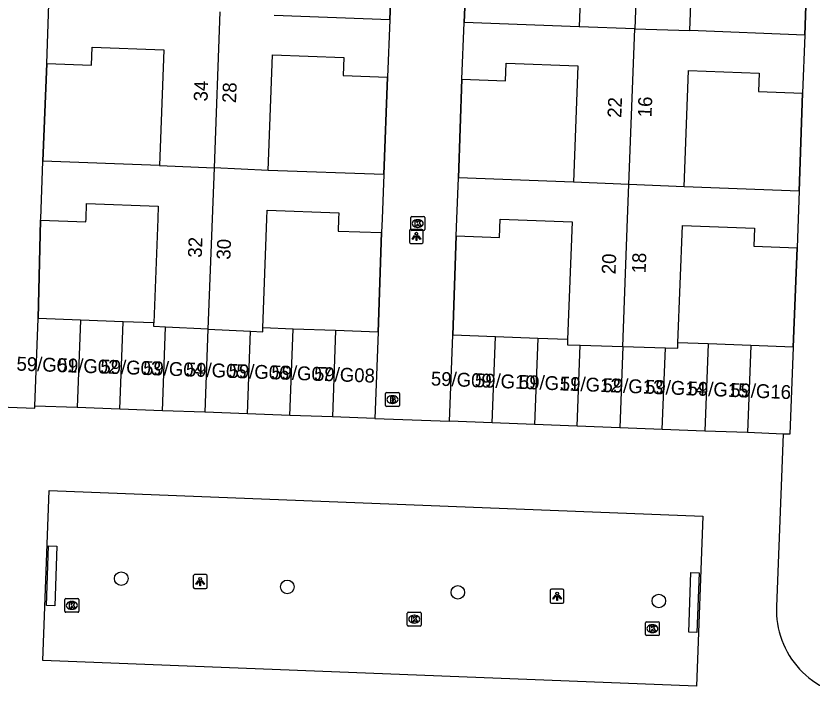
# Model space of a CAD drawing. Extents: x 160787 to 161428, y 386828 to 387483.
# Drawn here: x 161176.3 to 161233.8, y 387215.5 to 387264.6 of the extents above; entities that cross this region are included whole.
import ezdxf

# ---------------------------------------------------------------- set-up
doc = ezdxf.new("R2010")
doc.units = 0
for name, color, linetype in [('IMGEO_Boom', 7, 'Continuous'), ('IMGEO_Brandkraan', 7, 'Continuous'), ('IMGEO_Kolk', 7, 'Continuous'), ('IMGEO_Lichtpunt', 7, 'Continuous'), ('IMGEO_Muur', 7, 'Continuous'), ('IMGEO_Pand', 7, 'Continuous'), ('IMGEO_Pand_nummerreeks', 7, 'Continuous'), ('IMGEO_Parkeervlak_open', 7, 'Continuous'), ('IMGEO_Rijbaan_lokaal_open', 7, 'Continuous'), ('IMGEO_Voetpad_open', 7, 'Continuous')]:
    doc.layers.add(name, color=color, linetype=linetype)

msp = doc.modelspace()

# ---------------------------------------------------------------- linework, layer by layer
at = {"layer": 'IMGEO_Boom'}
for centre in [(161183.943, 387224.022), (161195.925, 387223.425), (161208.239, 387223.031), (161222.747, 387222.414)]:
    msp.add_circle(centre, 0.489, dxfattribs=at)
at = {"layer": 'IMGEO_Brandkraan'}
for p, q in [((161203.095, 387237.448), (161203.947, 387237.448)), ((161203.02, 387236.522), (161203.02, 387237.374)), ((161203.508, 387237.228), (161203.533, 387237.228)), ((161204.021, 387237.374), (161204.021, 387236.522)), ((161203.947, 387236.448), (161203.095, 387236.448)), ((161203.531, 387236.668), (161203.506, 387236.668))]:
    msp.add_line(p, q, dxfattribs=at)
for points in [[(161203.095, 387237.448), (161203.947, 387237.448)], [(161203.02, 387236.522), (161203.02, 387237.374)], [(161203.368, 387237.148), (161203.368, 387236.748), (161203.581, 387236.748)], [(161203.599, 387237.148), (161203.368, 387237.148)], [(161203.547, 387237.067), (161203.493, 387237.067), (161203.493, 387236.991)], [(161203.493, 387236.991), (161203.546, 387236.991)], [(161203.555, 387236.915), (161203.493, 387236.915), (161203.493, 387236.834)], [(161203.493, 387236.834), (161203.555, 387236.834)], [(161204.021, 387237.374), (161204.021, 387236.522)], [(161203.947, 387236.448), (161203.095, 387236.448)]]:
    msp.add_lwpolyline(points, dxfattribs=at)
for centre, radius, start, end in [((161203.097, 387237.372), 0.0765, 91.55205, 178.44795), ((161203.097, 387237.372), 0.0765, 91.55205, 178.44795), ((161203.945, 387237.372), 0.0765, 1.55205, 88.44795), ((161203.945, 387237.372), 0.0765, 1.55205, 88.44795), ((161203.548, 387237.029), 0.0379, 267.82845, 90.93552), ((161203.556, 387236.874), 0.0404, 269.87594, 90.50774), ((161203.603, 387237.003), 0.145, 59.4692, 91.53667), ((161203.628, 387237.05), 0.0922, 285.51372, 58.15012), ((161203.633, 387236.858), 0.105, 301.31148, 78.98903), ((161203.097, 387236.524), 0.0765, 181.55205, 268.44795), ((161203.097, 387236.524), 0.0765, 181.55205, 268.44795), ((161203.587, 387236.999), 0.251, 268.66757, 293.53466), ((161203.945, 387236.524), 0.0765, 271.55205, 358.44795), ((161203.945, 387236.524), 0.0765, 271.55205, 358.44795)]:
    msp.add_arc(centre, radius, start, end, dxfattribs=at)
for centre, major_axis, ratio, start_param, end_param in [((161203.507, 387236.948), (-0.387, 0.002), 0.722429, 4.712389, 7.853982), ((161203.532, 387236.948), (-0.39, 0.002), 0.717154, 1.570796, 4.712389)]:
    msp.add_ellipse(centre, major_axis=major_axis, ratio=ratio, start_param=start_param, end_param=end_param, dxfattribs=at)
at = {"layer": 'IMGEO_Kolk'}
for p, q in [((161204.844, 387249.228), (161204.844, 387250.08)), ((161204.919, 387250.154), (161205.771, 387250.154)), ((161205.845, 387250.08), (161205.845, 387249.228)), ((161205.332, 387249.934), (161205.357, 387249.934)), ((161205.771, 387249.154), (161204.919, 387249.154)), ((161205.355, 387249.374), (161205.33, 387249.374)), ((161179.877, 387221.665), (161179.877, 387222.517)), ((161179.952, 387222.591), (161180.804, 387222.591)), ((161180.878, 387222.517), (161180.878, 387221.665)), ((161180.365, 387222.371), (161180.39, 387222.371)), ((161180.804, 387221.591), (161179.952, 387221.591)), ((161180.388, 387221.811), (161180.363, 387221.811)), ((161204.592, 387220.673), (161204.592, 387221.525)), ((161204.667, 387221.599), (161205.519, 387221.599)), ((161205.08, 387221.379), (161205.105, 387221.379)), ((161205.593, 387221.525), (161205.593, 387220.673)), ((161205.103, 387220.819), (161205.078, 387220.819)), ((161221.779, 387219.985), (161221.779, 387220.837)), ((161221.854, 387220.911), (161222.706, 387220.911)), ((161222.78, 387220.837), (161222.78, 387219.985)), ((161205.519, 387220.599), (161204.667, 387220.599)), ((161222.267, 387220.691), (161222.292, 387220.691)), ((161222.706, 387219.911), (161221.854, 387219.911)), ((161222.29, 387220.131), (161222.265, 387220.131))]:
    msp.add_line(p, q, dxfattribs=at)
for points in [[(161204.844, 387249.228), (161204.844, 387250.08)], [(161204.919, 387250.154), (161205.771, 387250.154)], [(161205.845, 387250.08), (161205.845, 387249.228)], [(161205.165, 387249.854), (161205.288, 387249.854), (161205.288, 387249.703), (161205.418, 387249.854), (161205.582, 387249.854), (161205.436, 387249.703), (161205.589, 387249.454), (161205.437, 387249.454), (161205.352, 387249.618), (161205.288, 387249.551), (161205.288, 387249.454), (161205.165, 387249.454), (161205.165, 387249.854)], [(161205.771, 387249.154), (161204.919, 387249.154)], [(161179.877, 387221.665), (161179.877, 387222.517)], [(161179.952, 387222.591), (161180.804, 387222.591)], [(161180.878, 387222.517), (161180.878, 387221.665)], [(161180.198, 387222.291), (161180.321, 387222.291), (161180.321, 387222.14), (161180.451, 387222.291), (161180.615, 387222.291), (161180.469, 387222.14), (161180.622, 387221.891), (161180.47, 387221.891), (161180.385, 387222.055), (161180.321, 387221.988), (161180.321, 387221.891), (161180.198, 387221.891), (161180.198, 387222.291)], [(161180.804, 387221.591), (161179.952, 387221.591)], [(161204.592, 387220.673), (161204.592, 387221.525)], [(161204.667, 387221.599), (161205.519, 387221.599)], [(161205.593, 387221.525), (161205.593, 387220.673)], [(161204.913, 387221.299), (161205.036, 387221.299), (161205.036, 387221.148), (161205.166, 387221.299), (161205.33, 387221.299), (161205.184, 387221.148), (161205.337, 387220.899), (161205.185, 387220.899), (161205.1, 387221.063), (161205.036, 387220.996), (161205.036, 387220.899), (161204.913, 387220.899), (161204.913, 387221.299)], [(161221.779, 387219.985), (161221.779, 387220.837)], [(161221.854, 387220.911), (161222.706, 387220.911)], [(161222.78, 387220.837), (161222.78, 387219.985)], [(161205.519, 387220.599), (161204.667, 387220.599)], [(161222.1, 387220.611), (161222.223, 387220.611), (161222.223, 387220.46), (161222.353, 387220.611), (161222.517, 387220.611), (161222.371, 387220.46), (161222.524, 387220.211), (161222.372, 387220.211), (161222.287, 387220.375), (161222.223, 387220.308), (161222.223, 387220.211), (161222.1, 387220.211), (161222.1, 387220.611)], [(161222.706, 387219.911), (161221.854, 387219.911)]]:
    msp.add_lwpolyline(points, dxfattribs=at)
for centre, start, end in [((161204.921, 387250.078), 91.55205, 178.44795), ((161204.921, 387250.078), 91.55205, 178.44795), ((161205.769, 387250.078), 1.55205, 88.44795), ((161205.769, 387250.078), 1.55205, 88.44795), ((161204.921, 387249.23), 181.55205, 268.44795), ((161204.921, 387249.23), 181.55205, 268.44795), ((161205.769, 387249.23), 271.55205, 358.44795), ((161205.769, 387249.23), 271.55205, 358.44795), ((161179.954, 387222.515), 91.55205, 178.44795), ((161179.954, 387222.515), 91.55205, 178.44795), ((161180.802, 387222.515), 1.55205, 88.44795), ((161180.802, 387222.515), 1.55205, 88.44795), ((161179.954, 387221.667), 181.55205, 268.44795), ((161179.954, 387221.667), 181.55205, 268.44795), ((161180.802, 387221.667), 271.55205, 358.44795), ((161180.802, 387221.667), 271.55205, 358.44795), ((161204.669, 387221.523), 91.55205, 178.44795), ((161204.669, 387221.523), 91.55205, 178.44795), ((161205.517, 387221.523), 1.55205, 88.44795), ((161205.517, 387221.523), 1.55205, 88.44795), ((161221.856, 387220.835), 91.55205, 178.44795), ((161221.856, 387220.835), 91.55205, 178.44795), ((161222.704, 387220.835), 1.55205, 88.44795), ((161222.704, 387220.835), 1.55205, 88.44795), ((161204.669, 387220.675), 181.55205, 268.44795), ((161204.669, 387220.675), 181.55205, 268.44795), ((161205.517, 387220.675), 271.55205, 358.44795), ((161205.517, 387220.675), 271.55205, 358.44795), ((161221.856, 387219.987), 181.55205, 268.44795), ((161221.856, 387219.987), 181.55205, 268.44795), ((161222.704, 387219.987), 271.55205, 358.44795), ((161222.704, 387219.987), 271.55205, 358.44795)]:
    msp.add_arc(centre, 0.0765, start, end, dxfattribs=at)
for centre, major_axis, ratio, start_param, end_param in [((161205.331, 387249.654), (-0.387, 0.002), 0.722429, 4.712389, 7.853982), ((161205.356, 387249.654), (-0.39, 0.002), 0.717154, 1.570796, 4.712389), ((161180.364, 387222.091), (-0.387, 0.002), 0.722429, 4.712389, 7.853982), ((161180.389, 387222.091), (-0.39, 0.002), 0.717154, 1.570796, 4.712389), ((161205.079, 387221.099), (-0.387, 0.002), 0.722429, 4.712389, 7.853982), ((161205.104, 387221.099), (-0.39, 0.002), 0.717154, 1.570796, 4.712389), ((161222.266, 387220.411), (-0.387, 0.002), 0.722429, 4.712389, 7.853982), ((161222.291, 387220.411), (-0.39, 0.002), 0.717154, 1.570796, 4.712389)]:
    msp.add_ellipse(centre, major_axis=major_axis, ratio=ratio, start_param=start_param, end_param=end_param, dxfattribs=at)
at = {"layer": 'IMGEO_Lichtpunt'}
for p, q in [((161204.744, 387249.126), (161204.744, 387248.319)), ((161204.744, 387249.126), (161204.744, 387248.319)), ((161205.646, 387249.221), (161204.838, 387249.221)), ((161205.646, 387249.221), (161204.838, 387249.221)), ((161205.74, 387248.319), (161205.74, 387249.126)), ((161205.74, 387248.319), (161205.74, 387249.126)), ((161204.838, 387248.225), (161205.646, 387248.225)), ((161204.838, 387248.225), (161205.646, 387248.225)), ((161189.146, 387224.217), (161189.146, 387223.41)), ((161189.146, 387224.217), (161189.146, 387223.41)), ((161190.048, 387224.312), (161189.24, 387224.312)), ((161190.048, 387224.312), (161189.24, 387224.312)), ((161190.142, 387223.41), (161190.142, 387224.217)), ((161190.142, 387223.41), (161190.142, 387224.217)), ((161189.24, 387223.316), (161190.048, 387223.316)), ((161189.24, 387223.316), (161190.048, 387223.316)), ((161214.901, 387223.159), (161214.901, 387222.352)), ((161214.901, 387223.159), (161214.901, 387222.352)), ((161215.803, 387223.254), (161214.995, 387223.254)), ((161215.803, 387223.254), (161214.995, 387223.254)), ((161215.897, 387222.352), (161215.897, 387223.159)), ((161215.897, 387222.352), (161215.897, 387223.159)), ((161214.995, 387222.258), (161215.803, 387222.258)), ((161214.995, 387222.258), (161215.803, 387222.258))]:
    msp.add_line(p, q, dxfattribs=at)
for points in [[(161205.118, 387248.79), (161205.157, 387248.762), (161204.969, 387248.5), (161204.931, 387248.527), (161205.118, 387248.79)], [(161205.22, 387248.742), (161205.267, 387248.742), (161205.267, 387248.42), (161205.22, 387248.42), (161205.22, 387248.742)], [(161205.33, 387248.762), (161205.368, 387248.789), (161205.555, 387248.527), (161205.516, 387248.499), (161205.33, 387248.762)], [(161189.52, 387223.881), (161189.559, 387223.853), (161189.371, 387223.591), (161189.333, 387223.618), (161189.52, 387223.881)], [(161189.622, 387223.833), (161189.669, 387223.833), (161189.669, 387223.511), (161189.622, 387223.511), (161189.622, 387223.833)], [(161189.732, 387223.853), (161189.77, 387223.88), (161189.957, 387223.618), (161189.918, 387223.59), (161189.732, 387223.853)], [(161215.275, 387222.823), (161215.314, 387222.795), (161215.126, 387222.533), (161215.088, 387222.56), (161215.275, 387222.823)], [(161215.377, 387222.775), (161215.424, 387222.775), (161215.424, 387222.453), (161215.377, 387222.453), (161215.377, 387222.775)], [(161215.487, 387222.795), (161215.525, 387222.822), (161215.712, 387222.56), (161215.673, 387222.532), (161215.487, 387222.795)]]:
    msp.add_lwpolyline(points, dxfattribs=at)
for centre in [(161205.243, 387248.924), (161189.645, 387224.015), (161215.4, 387222.957)]:
    msp.add_circle(centre, 0.0994, dxfattribs=at)
for centre, start, end in [((161204.838, 387249.126), 90, 180), ((161204.838, 387249.126), 90, 180), ((161205.646, 387249.126), 0, 90), ((161205.646, 387249.126), 0, 90), ((161204.838, 387248.319), 180, 270), ((161204.838, 387248.319), 180, 270), ((161205.646, 387248.319), 270, 0), ((161205.646, 387248.319), 270, 360), ((161189.24, 387224.217), 90, 180), ((161189.24, 387224.217), 90, 180), ((161190.048, 387224.217), 0, 90), ((161190.048, 387224.217), 0, 90), ((161189.24, 387223.41), 180, 270), ((161189.24, 387223.41), 180, 270), ((161190.048, 387223.41), 270, 0), ((161190.048, 387223.41), 270, 360), ((161214.995, 387223.159), 90, 180), ((161214.995, 387223.159), 90, 180), ((161215.803, 387223.159), 0, 90), ((161215.803, 387223.159), 0, 90), ((161214.995, 387222.352), 180, 270), ((161214.995, 387222.352), 180, 270), ((161215.803, 387222.352), 270, 0), ((161215.803, 387222.352), 270, 360)]:
    msp.add_arc(centre, 0.0946, start, end, dxfattribs=at)
at = {"layer": 'IMGEO_Muur'}
for points in [[(161203.32, 387264.366), (161203.604, 387271.548)], [(161209, 387271.312), (161208.693, 387264.163)], [(161233.272, 387263.261), (161233.524, 387270.355)], [(161178.566, 387261.216), (161178.282, 387254.158)], [(161202.892, 387253.186), (161203.167, 387260.218)], [(161208.537, 387260.082), (161208.287, 387252.962)], [(161232.882, 387251.985), (161233.112, 387259.06)], [(161178.125, 387249.896), (161177.936, 387242.793)], [(161202.486, 387241.811), (161202.738, 387248.999)], [(161208.127, 387248.761), (161207.876, 387241.591)], [(161232.45, 387240.729), (161232.726, 387247.901)]]:
    msp.add_lwpolyline(points, dxfattribs=at)
at = {"layer": 'IMGEO_Pand'}
for points in [[(161221.422, 387275.016), (161221.001, 387263.712)], [(161209, 387271.312), (161212.092, 387271.194), (161212.139, 387272.444), (161217.307, 387272.247), (161216.986, 387263.847)], [(161224.971, 387263.578), (161225.29, 387271.946), (161230.346, 387271.753), (161230.298, 387270.478), (161233.524, 387270.355)], [(161178.566, 387261.216), (161178.724, 387265.502)], [(161191.064, 387264.932), (161190.639, 387253.67)], [(161203.32, 387264.366), (161194.971, 387264.673)], [(161203.32, 387264.366), (161203.167, 387260.218)], [(161208.537, 387260.082), (161208.693, 387264.163)], [(161216.986, 387263.847), (161208.693, 387264.163)], [(161221.001, 387263.712), (161216.986, 387263.847)], [(161220.582, 387252.472), (161221.001, 387263.712)], [(161221.001, 387263.712), (161224.971, 387263.578)], [(161233.272, 387263.261), (161224.971, 387263.578)], [(161233.272, 387263.261), (161233.112, 387259.06)], [(161178.566, 387261.216), (161181.795, 387261.097), (161181.842, 387262.378), (161187.014, 387262.187), (161186.707, 387253.847)], [(161194.559, 387253.493), (161194.866, 387261.84), (161200.02, 387261.65), (161199.971, 387260.336), (161203.167, 387260.218)], [(161208.537, 387260.082), (161211.677, 387259.962), (161211.726, 387261.227), (161216.893, 387261.03), (161216.574, 387252.646)], [(161224.572, 387252.302), (161224.893, 387260.706), (161229.979, 387260.512), (161229.928, 387259.181), (161233.112, 387259.06)], [(161178.125, 387249.896), (161178.129, 387250), (161178.282, 387254.158)], [(161186.707, 387253.847), (161178.282, 387254.158)], [(161186.707, 387253.847), (161190.639, 387253.67)], [(161190.639, 387253.67), (161190.5, 387250), (161190.199, 387242.031)], [(161194.559, 387253.493), (161190.639, 387253.67)], [(161202.892, 387253.186), (161194.559, 387253.493)], [(161202.892, 387253.186), (161202.775, 387250), (161202.738, 387248.999)], [(161208.127, 387248.761), (161208.174, 387250), (161208.287, 387252.962)], [(161216.574, 387252.646), (161208.287, 387252.962)], [(161220.582, 387252.472), (161216.574, 387252.646)], [(161220.147, 387240.781), (161220.49, 387250), (161220.582, 387252.472)], [(161224.572, 387252.302), (161220.582, 387252.472)], [(161232.882, 387251.985), (161224.572, 387252.302)], [(161232.882, 387251.985), (161232.806, 387250), (161232.726, 387247.901)], [(161178.125, 387249.896), (161181.395, 387249.775), (161181.403, 387250), (161181.444, 387251.092), (161186.611, 387250.902), (161186.578, 387250), (161186.3, 387242.485)], [(161194.163, 387242.117), (161194.453, 387250), (161194.476, 387250.62), (161199.65, 387250.429), (161199.634, 387250), (161199.601, 387249.115), (161202.738, 387248.999)], [(161208.127, 387248.761), (161211.234, 387248.643), (161211.285, 387249.968), (161216.482, 387249.769), (161216.159, 387241.275)], [(161224.122, 387241.046), (161224.446, 387249.524), (161229.641, 387249.325), (161229.592, 387248.02), (161232.726, 387247.901)], [(161177.704, 387236.483), (161177.936, 387242.793)], [(161181.005, 387242.68), (161177.936, 387242.793)], [(161181.005, 387242.68), (161180.773, 387236.37)], [(161184.075, 387242.567), (161181.005, 387242.68)], [(161183.842, 387236.257), (161184.075, 387242.567)], [(161186.3, 387242.485), (161184.075, 387242.567)], [(161187.133, 387242.175), (161186.29, 387242.215), (161186.3, 387242.485)], [(161186.911, 387236.144), (161187.133, 387242.175)], [(161190.199, 387242.031), (161187.133, 387242.175)], [(161190.199, 387242.031), (161189.98, 387236.031)], [(161190.199, 387242.031), (161193.269, 387241.887)], [(161193.269, 387241.887), (161194.155, 387241.845), (161194.163, 387242.117)], [(161196.348, 387242.037), (161194.163, 387242.117)], [(161196.119, 387235.805), (161196.348, 387242.037)], [(161199.417, 387241.924), (161196.348, 387242.037)], [(161193.05, 387235.918), (161193.269, 387241.887)], [(161199.417, 387241.924), (161199.188, 387235.692)], [(161202.486, 387241.811), (161199.417, 387241.924)], [(161202.486, 387241.811), (161202.257, 387235.579)], [(161207.639, 387235.379), (161207.876, 387241.591)], [(161210.947, 387241.474), (161207.876, 387241.591)], [(161210.711, 387235.262), (161210.947, 387241.474)], [(161214.019, 387241.357), (161210.947, 387241.474)], [(161214.019, 387241.357), (161213.782, 387235.145)], [(161216.159, 387241.275), (161214.019, 387241.357)], [(161216.159, 387241.275), (161216.145, 387240.897), (161217.076, 387240.87)], [(161216.854, 387235.028), (161217.076, 387240.87)], [(161217.076, 387240.87), (161220.147, 387240.781)], [(161223.221, 387240.692), (161224.106, 387240.667), (161224.122, 387241.046)], [(161226.308, 387240.963), (161224.122, 387241.046)], [(161226.308, 387240.963), (161226.068, 387234.676)], [(161229.379, 387240.846), (161226.308, 387240.963)], [(161220.147, 387240.781), (161219.925, 387234.91)], [(161220.147, 387240.781), (161223.221, 387240.692)], [(161222.996, 387234.793), (161223.221, 387240.692)], [(161229.379, 387240.846), (161229.14, 387234.559)], [(161232.45, 387240.729), (161229.379, 387240.846)], [(161232.45, 387240.729), (161232.211, 387234.442), (161231.716, 387234.461)], [(161180.773, 387236.37), (161177.704, 387236.483)], [(161183.842, 387236.257), (161180.773, 387236.37)], [(161186.911, 387236.144), (161183.842, 387236.257)], [(161189.98, 387236.031), (161186.911, 387236.144)], [(161193.05, 387235.918), (161189.98, 387236.031)], [(161196.119, 387235.805), (161193.05, 387235.918)], [(161199.188, 387235.692), (161196.119, 387235.805)], [(161202.257, 387235.579), (161199.188, 387235.692)], [(161210.711, 387235.262), (161207.639, 387235.379)], [(161213.782, 387235.145), (161210.711, 387235.262)], [(161216.854, 387235.028), (161213.782, 387235.145)], [(161219.925, 387234.91), (161216.854, 387235.028)], [(161222.996, 387234.793), (161219.925, 387234.91)], [(161226.068, 387234.676), (161222.996, 387234.793)], [(161229.14, 387234.559), (161226.068, 387234.676)], [(161231.716, 387234.461), (161229.14, 387234.559)]]:
    msp.add_lwpolyline(points, dxfattribs=at)
at = {"layer": 'IMGEO_Parkeervlak_open'}
for points in [[(161179.144, 387222.07), (161178.544, 387222.092), (161178.704, 387226.389), (161179.304, 387226.367), (161179.144, 387222.07)], [(161225.498, 387220.135), (161224.898, 387220.158), (161225.058, 387224.455), (161225.658, 387224.432), (161225.498, 387220.135)]]:
    msp.add_lwpolyline(points, dxfattribs=at)
at = {"layer": 'IMGEO_Rijbaan_lokaal_open'}
for points in [[(161172.518, 387236.516), (161173.243, 387236.489), (161177.698, 387236.325), (161177.704, 387236.483)], [(161202.257, 387235.579), (161207.639, 387235.379)], [(161231.716, 387234.461), (161231.242, 387222.012)], [(161225.454, 387216.265), (161178.296, 387218.105), (161178.753, 387230.391), (161225.91, 387228.525), (161225.454, 387216.265)]]:
    msp.add_lwpolyline(points, dxfattribs=at)
msp.add_arc((161237.517, 387221.748), 6.28, 177.58886, 267.7928, dxfattribs=at)
at = {"layer": 'IMGEO_Voetpad_open'}
for points in [[(161203.604, 387271.548), (161203.32, 387264.366)], [(161208.693, 387264.163), (161209, 387271.312)], [(161233.524, 387270.355), (161233.272, 387263.261)], [(161178.282, 387254.158), (161178.566, 387261.216)], [(161203.167, 387260.218), (161202.892, 387253.186)], [(161208.287, 387252.962), (161208.537, 387260.082)], [(161233.112, 387259.06), (161232.882, 387251.985)], [(161177.936, 387242.793), (161178.125, 387249.896)], [(161202.738, 387248.999), (161202.486, 387241.811)], [(161207.876, 387241.591), (161208.127, 387248.761)], [(161232.726, 387247.901), (161232.45, 387240.729)]]:
    msp.add_lwpolyline(points, dxfattribs=at)

# ---------------------------------------------------------------- texts
at = {"layer": 'IMGEO_Pand_nummerreeks'}
for s, rotation, p in [('34', 87.89374, (161190.169, 387258.456)), ('28', 87.92901, (161192.228, 387258.341)), ('22', 87.8716, (161220.036, 387257.272)), ('16', 87.8337, (161222.216, 387257.316)), ('32', 87.89374, (161189.754, 387247.175)), ('30', 87.92901, (161191.819, 387247.038)), ('20', 87.8716, (161219.616, 387245.979)), ('18', 87.8337, (161221.789, 387246.046)), ('59/G01', 358.06507, (161176.372, 387239.042)), ('59/G02', 358.06507, (161179.338, 387238.941)), ('59/G03', 358.06507, (161182.428, 387238.837)), ('59/G04', 358.06507, (161185.511, 387238.733)), ('59/G05', 358.06507, (161188.595, 387238.629)), ('59/G06', 358.06507, (161191.678, 387238.524)), ('59/G07', 358.06507, (161194.761, 387238.42)), ('59/G08', 358.06507, (161197.848, 387238.316)), ('59/G09', 357.81576, (161206.281, 387237.97)), ('59/G10', 357.81576, (161209.45, 387237.849)), ('59/G11', 357.81576, (161212.63, 387237.728)), ('59/G12', 357.81576, (161215.585, 387237.615)), ('59/G13', 357.81576, (161218.664, 387237.498)), ('59/G14', 357.81576, (161221.736, 387237.381)), ('59/G15', 357.81576, (161224.808, 387237.263)), ('59/G16', 357.81703, (161227.881, 387237.146))]:
    msp.add_text(s, height=1, rotation=rotation, dxfattribs=at).set_placement(p)

doc.saveas('drawing.dxf')
